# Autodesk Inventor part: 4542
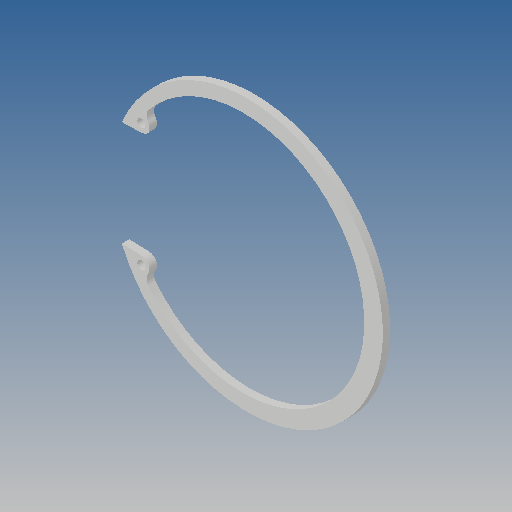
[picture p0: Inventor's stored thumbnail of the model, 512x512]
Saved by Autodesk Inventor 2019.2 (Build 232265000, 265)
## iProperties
Created: 2013-07
Part Number: 4542
Material: Ogólny
Document SubType Name: Modeling
Designer: CADENGINEERING4
Density: 1 g/cm^3
Appearance: Domyślna
Author: CADENGINEERING4
Revision Number: ÈÎºÎ
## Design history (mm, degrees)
feature "Í¹Ì¨-À­Éì1"
node "Bryła1"
